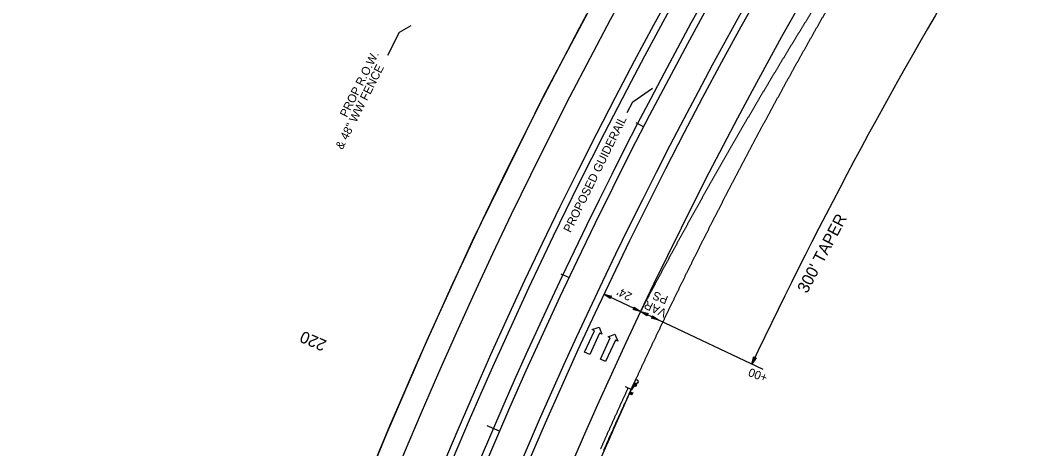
# Model space of a CAD drawing. Extents: x 2389099 to 2405615, y 552200 to 573532.
# Drawn here: x 2400105 to 2400699, y 569173 to 569428 of the extents above; entities that cross this region are included whole.
import ezdxf

# ---------------------------------------------------------------- set-up
doc = ezdxf.new("R2010")
doc.units = 0
for name, color, linetype in [('Old_Level_1', 7, 'Continuous'), ('Prop Cable Guiderail Single Face', 7, 'Continuous'), ('Prop Conc Expressway Gutter', 7, 'Continuous'), ('Prop Dimension', 7, 'Continuous'), ('Prop Dimension Text', 7, 'Continuous'), ('Prop DSN Text', 7, 'Continuous'), ('Prop EOT', 7, 'Continuous'), ('Prop Guardrail', 7, 'Continuous'), ('Prop Horizontal Alignment', 7, 'Continuous'), ('Prop Horizontal Alignment Curve and Spiral Data', 7, 'Continuous'), ('Prop Horizontal Alignment Tick Large', 7, 'Continuous'), ('Prop Horizontal Alignment Tick Small', 7, 'Continuous'), ('Prop Lane Arrow Through CELL', 7, 'Continuous'), ('Prop Lane Lines', 7, 'Continuous')]:
    doc.layers.add(name, color=color, linetype=linetype)

msp = doc.modelspace()

# ---------------------------------------------------------------- linework, layer by layer
at = {"layer": 'Old_Level_1'}
for p, q in [((2400468.37, 569210.69), (2400468.94, 569211.96)), ((2400468.83, 569211.72), (2400469.54, 569213.29)), ((2400468.94, 569211.96), (2400470.41, 569211.3)), ((2400468.94, 569211.96), (2400469.84, 569210.02)), ((2400470.66, 569211.91), (2400469.59, 569211.67)), ((2400466.06, 569205.59), (2400468.83, 569211.72)), ((2400466.06, 569205.59), (2400466.64, 569206.87)), ((2400466.06, 569205.59), (2400468.11, 569206.2)), ((2400466.64, 569206.87), (2400468.11, 569206.2)), ((2400466.64, 569206.87), (2400467.53, 569204.93)), ((2400469.39, 569210.99), (2400467.09, 569207.86)), ((2400468.11, 569206.2), (2400467.53, 569204.93)), ((2400468.37, 569210.69), (2400470.41, 569211.3)), ((2400469.84, 569210.02), (2400468.37, 569210.69)), ((2400468.83, 569211.72), (2400468.72, 569211.48)), ((2400470.41, 569211.3), (2400469.84, 569210.02)), ((2400467.53, 569204.93), (2400466.06, 569205.59))]:
    msp.add_line(p, q, dxfattribs=at)
msp.add_ellipse((2400470.45, 569212.88), major_axis=(-0.905, 0.409), ratio=0.995379, start_param=2.210226, end_param=6.283185, dxfattribs=at)
at = {"layer": 'Prop Cable Guiderail Single Face'}
msp.add_arc((2403051.7, 568034.46), 2904, 119.41161, 162.0892, dxfattribs=at)
at = {"layer": 'Prop Conc Expressway Gutter'}
msp.add_spline([(2400449.06, 569172.84), (2400449.4, 569173.61), (2400449.75, 569174.39), (2400450.09, 569175.17), (2400450.44, 569175.95), (2400450.79, 569176.73), (2400451.13, 569177.51), (2400451.48, 569178.29), (2400451.83, 569179.07), (2400452.17, 569179.83), (2400452.52, 569180.61), (2400452.86, 569181.39), (2400453.21, 569182.17), (2400453.56, 569182.95), (2400453.91, 569183.73), (2400454.26, 569184.5), (2400454.6, 569185.28), (2400454.95, 569186.05), (2400455.3, 569186.83), (2400455.65, 569187.6), (2400456, 569188.38), (2400456.35, 569189.16), (2400456.7, 569189.93), (2400457.05, 569190.71), (2400457.4, 569191.49), (2400457.75, 569192.26), (2400458.1, 569193.03), (2400458.45, 569193.81), (2400458.8, 569194.59), (2400459.15, 569195.36), (2400459.5, 569196.14), (2400459.85, 569196.91), (2400460.2, 569197.68), (2400460.56, 569198.46), (2400460.91, 569199.23), (2400461.26, 569200.01), (2400461.61, 569200.78), (2400461.97, 569201.56), (2400462.32, 569202.33), (2400462.68, 569203.11), (2400463.03, 569203.88), (2400463.38, 569204.65), (2400463.74, 569205.43), (2400464.09, 569206.2), (2400464.45, 569206.97), (2400464.8, 569207.75), (2400465.16, 569208.52), (2400465.41, 569209.08)], degree=3, dxfattribs=at)
at = {"layer": 'Prop Dimension'}
for p, q in [((2400472.73, 569254.5), (2400451.03, 569264.77)), ((2400483.58, 569249.37), (2400472.73, 569254.5)), ((2400545.52, 569220.07), (2400483.58, 569249.37))]:
    msp.add_line(p, q, dxfattribs=at)
for points in [[(2400454.77, 569262.14), (2400451.03, 569264.77), (2400455.47, 569263.55), (2400454.6, 569263.08)], [(2400468.99, 569257.13), (2400472.73, 569254.5), (2400468.3, 569255.71), (2400469.16, 569256.19)], [(2400476.47, 569251.88), (2400472.73, 569254.5), (2400477.16, 569253.29), (2400476.3, 569252.81)], [(2400479.84, 569252), (2400483.58, 569249.37), (2400479.14, 569250.58), (2400480.01, 569251.06)], [(2400541.27, 569227.07), (2400538.71, 569223.29), (2400539.84, 569227.74), (2400540.33, 569226.89)]]:
    msp.add_lwpolyline(points, close=True, dxfattribs=at)
msp.add_arc((2403051.7, 568034.46), 2780, 148.7553, 154.68244, dxfattribs=at)
at = {"layer": 'Prop DSN Text'}
for p, q in [((2400322.78, 569406.64), (2400329.86, 569420.33)), ((2400329.86, 569420.33), (2400336.73, 569424.27)), ((2400468.1, 569379.06), (2400479.81, 569387.11)), ((2400464.71, 569372.74), (2400468.1, 569379.06))]:
    msp.add_line(p, q, dxfattribs=at)
at = {"layer": 'Prop EOT'}
msp.add_line((2400463.6, 569209.92), (2400467.29, 569208.22), dxfattribs=at)
for radius, start, end in [(2923, 119.41161, 180.94658), (2919, 119.41161, 162.43732), (2881, 119.41161, 165.38993), (2877, 119.41161, 180.94658), (2961, 148.75529, 167.84172), (2947, 148.75529, 180.94658), (2853, 154.68245, 180.94658)]:
    msp.add_arc((2403051.7, 568034.46), radius, start, end, dxfattribs=at)
for points in [[(2400590.72, 569458.71), (2400590.29, 569458.04), (2400589.87, 569457.36), (2400589.44, 569456.69), (2400589.02, 569456.02), (2400588.59, 569455.35), (2400588.17, 569454.68), (2400587.74, 569454), (2400587.31, 569453.33), (2400586.89, 569452.65), (2400586.46, 569451.98), (2400586.04, 569451.31), (2400585.62, 569450.64), (2400585.19, 569449.96), (2400584.77, 569449.29), (2400584.35, 569448.62), (2400583.92, 569447.94), (2400583.5, 569447.27), (2400583.08, 569446.6), (2400582.65, 569445.92), (2400582.23, 569445.24), (2400581.81, 569444.57), (2400581.38, 569443.89), (2400580.96, 569443.22), (2400580.54, 569442.55), (2400580.12, 569441.87), (2400579.7, 569441.2), (2400579.28, 569440.52), (2400578.86, 569439.85), (2400578.44, 569439.17), (2400578.02, 569438.5), (2400577.59, 569437.82), (2400577.17, 569437.14), (2400576.75, 569436.47), (2400576.33, 569435.79), (2400575.91, 569435.11), (2400575.49, 569434.44), (2400575.07, 569433.76), (2400574.65, 569433.09), (2400574.23, 569432.41), (2400573.82, 569431.74), (2400573.4, 569431.06), (2400572.98, 569430.38), (2400572.56, 569429.71), (2400572.14, 569429.02), (2400571.72, 569428.34), (2400571.3, 569427.67), (2400570.89, 569426.99), (2400570.47, 569426.31), (2400570.05, 569425.64), (2400569.64, 569424.96), (2400569.22, 569424.28), (2400568.8, 569423.6), (2400568.39, 569422.93), (2400567.97, 569422.25), (2400567.55, 569421.57), (2400567.13, 569420.88), (2400566.72, 569420.21), (2400566.3, 569419.53), (2400565.89, 569418.85), (2400565.47, 569418.17), (2400565.06, 569417.49), (2400564.64, 569416.81), (2400564.23, 569416.13), (2400563.81, 569415.45), (2400563.4, 569414.78), (2400562.99, 569414.1), (2400562.57, 569413.42), (2400562.16, 569412.73), (2400561.74, 569412.05), (2400561.33, 569411.37), (2400560.92, 569410.69), (2400560.5, 569410.01), (2400560.09, 569409.33), (2400559.68, 569408.65)], [(2400562.85, 569397.33), (2400563.26, 569398.07), (2400563.67, 569398.81), (2400564.08, 569399.55), (2400564.49, 569400.3), (2400564.91, 569401.04), (2400565.32, 569401.78), (2400565.73, 569402.53), (2400566.15, 569403.27), (2400566.56, 569404.02), (2400566.97, 569404.76), (2400567.38, 569405.49), (2400567.8, 569406.24), (2400568.21, 569406.98), (2400568.63, 569407.72), (2400569.05, 569408.47), (2400569.46, 569409.21), (2400569.88, 569409.95), (2400570.29, 569410.69), (2400570.7, 569411.43), (2400571.12, 569412.17), (2400571.54, 569412.91), (2400571.96, 569413.66), (2400572.37, 569414.4), (2400572.79, 569415.14), (2400573.21, 569415.88), (2400573.63, 569416.62), (2400574.04, 569417.36), (2400574.46, 569418.1), (2400574.88, 569418.84), (2400575.29, 569419.58), (2400575.71, 569420.32), (2400576.13, 569421.06), (2400576.55, 569421.8), (2400576.97, 569422.54), (2400577.39, 569423.27), (2400577.81, 569424.01), (2400578.23, 569424.75), (2400578.65, 569425.49), (2400579.07, 569426.23), (2400579.49, 569426.97), (2400579.91, 569427.71), (2400580.33, 569428.45), (2400580.75, 569429.18), (2400581.17, 569429.92), (2400581.59, 569430.66), (2400582.02, 569431.4), (2400582.44, 569432.14), (2400582.86, 569432.88), (2400583.28, 569433.62), (2400583.7, 569434.35), (2400584.13, 569435.09), (2400584.55, 569435.83), (2400584.97, 569436.56), (2400585.4, 569437.3), (2400585.82, 569438.04), (2400586.25, 569438.78), (2400586.67, 569439.52), (2400587.09, 569440.24), (2400587.52, 569440.98), (2400587.94, 569441.72), (2400588.37, 569442.46), (2400588.79, 569443.19), (2400589.22, 569443.93), (2400589.65, 569444.67), (2400590.07, 569445.4), (2400590.49, 569446.13), (2400590.92, 569446.87), (2400591.35, 569447.6), (2400591.78, 569448.34), (2400592.2, 569449.08), (2400592.63, 569449.81), (2400593.06, 569450.55), (2400593.49, 569451.28), (2400593.91, 569452.01)], [(2400559.68, 569408.65), (2400559.27, 569407.97), (2400558.85, 569407.29), (2400558.44, 569406.61), (2400558.03, 569405.93), (2400557.62, 569405.24), (2400557.21, 569404.56), (2400556.79, 569403.87), (2400556.38, 569403.19), (2400555.97, 569402.51), (2400555.56, 569401.83), (2400555.15, 569401.15), (2400554.74, 569400.47), (2400554.33, 569399.78), (2400553.92, 569399.1), (2400553.51, 569398.42), (2400553.1, 569397.74), (2400552.69, 569397.06), (2400552.28, 569396.37), (2400551.87, 569395.68), (2400551.46, 569395), (2400551.05, 569394.32), (2400550.65, 569393.63), (2400550.24, 569392.95), (2400549.83, 569392.27), (2400549.42, 569391.58), (2400549.01, 569390.9), (2400548.61, 569390.22), (2400548.2, 569389.53), (2400547.79, 569388.85), (2400547.39, 569388.16), (2400546.98, 569387.47), (2400546.57, 569386.79), (2400546.16, 569386.1), (2400545.76, 569385.42), (2400545.35, 569384.73), (2400544.95, 569384.05), (2400544.54, 569383.36), (2400544.13, 569382.68), (2400543.73, 569381.99), (2400543.32, 569381.31), (2400542.92, 569380.62), (2400542.52, 569379.94), (2400542.11, 569379.25), (2400541.7, 569378.56), (2400541.3, 569377.87), (2400540.9, 569377.19), (2400540.49, 569376.5), (2400540.09, 569375.81), (2400539.68, 569375.13), (2400539.28, 569374.44), (2400538.88, 569373.75), (2400538.48, 569373.07), (2400538.07, 569372.38), (2400537.67, 569371.69), (2400537.27, 569371.01), (2400536.86, 569370.31), (2400536.46, 569369.62), (2400536.06, 569368.94), (2400535.66, 569368.25), (2400535.26, 569367.56), (2400534.86, 569366.87), (2400534.46, 569366.19), (2400534.06, 569365.5), (2400533.66, 569364.81), (2400533.25, 569364.12), (2400532.85, 569363.43), (2400532.46, 569362.74), (2400532.05, 569362.05), (2400531.65, 569361.36), (2400531.25, 569360.67), (2400530.85, 569359.98), (2400530.45, 569359.29), (2400530.06, 569358.6), (2400529.66, 569357.91)], [(2400532.99, 569341.95), (2400533.39, 569342.71), (2400533.78, 569343.46), (2400534.18, 569344.21), (2400534.58, 569344.97), (2400534.97, 569345.72), (2400535.37, 569346.47), (2400535.76, 569347.22), (2400536.16, 569347.97), (2400536.56, 569348.72), (2400536.96, 569349.48), (2400537.35, 569350.23), (2400537.75, 569350.98), (2400538.15, 569351.73), (2400538.55, 569352.48), (2400538.94, 569353.23), (2400539.34, 569353.98), (2400539.74, 569354.73), (2400540.14, 569355.48), (2400540.54, 569356.24), (2400540.94, 569356.99), (2400541.34, 569357.74), (2400541.74, 569358.48), (2400542.14, 569359.23), (2400542.54, 569359.98), (2400542.94, 569360.73), (2400543.34, 569361.48), (2400543.74, 569362.24), (2400544.15, 569362.99), (2400544.55, 569363.74), (2400544.95, 569364.48), (2400545.35, 569365.23), (2400545.75, 569365.98), (2400546.15, 569366.73), (2400546.56, 569367.48), (2400546.96, 569368.23), (2400547.36, 569368.98), (2400547.77, 569369.73), (2400548.17, 569370.47), (2400548.57, 569371.22), (2400548.98, 569371.97), (2400549.38, 569372.71), (2400549.79, 569373.46), (2400550.19, 569374.21), (2400550.6, 569374.96), (2400551, 569375.71), (2400551.4, 569376.45), (2400551.81, 569377.2), (2400552.22, 569377.94), (2400552.62, 569378.69), (2400553.03, 569379.44), (2400553.44, 569380.19), (2400553.84, 569380.94), (2400554.25, 569381.68), (2400554.66, 569382.42), (2400555.06, 569383.17), (2400555.47, 569383.92), (2400555.88, 569384.66), (2400556.29, 569385.41), (2400556.7, 569386.16), (2400557.11, 569386.9), (2400557.52, 569387.65), (2400557.92, 569388.39), (2400558.33, 569389.13), (2400558.74, 569389.88), (2400559.15, 569390.63), (2400559.56, 569391.37), (2400559.97, 569392.12), (2400560.38, 569392.86), (2400560.79, 569393.6), (2400561.2, 569394.35), (2400561.61, 569395.09), (2400562.02, 569395.84), (2400562.43, 569396.58), (2400562.85, 569397.33)], [(2400529.66, 569357.91), (2400529.26, 569357.22), (2400528.86, 569356.53), (2400528.46, 569355.84), (2400528.07, 569355.16), (2400527.67, 569354.47), (2400527.27, 569353.78), (2400526.87, 569353.08), (2400526.47, 569352.39), (2400526.08, 569351.7), (2400525.68, 569351.01), (2400525.28, 569350.31), (2400524.89, 569349.62), (2400524.49, 569348.93), (2400524.09, 569348.24), (2400523.7, 569347.55), (2400523.3, 569346.86), (2400522.91, 569346.17), (2400522.51, 569345.48), (2400522.11, 569344.78), (2400521.72, 569344.08), (2400521.32, 569343.39), (2400520.93, 569342.7), (2400520.54, 569342.01), (2400520.14, 569341.32), (2400519.75, 569340.62), (2400519.35, 569339.93), (2400518.96, 569339.24), (2400518.57, 569338.55), (2400518.18, 569337.85), (2400517.78, 569337.16), (2400517.39, 569336.46), (2400516.99, 569335.77), (2400516.6, 569335.07), (2400516.21, 569334.38), (2400515.82, 569333.69), (2400515.43, 569332.99), (2400515.03, 569332.3), (2400514.64, 569331.61), (2400514.25, 569330.91), (2400513.86, 569330.22), (2400513.47, 569329.52), (2400513.08, 569328.83), (2400512.69, 569328.14), (2400512.29, 569327.43), (2400511.9, 569326.74), (2400511.51, 569326.04), (2400511.12, 569325.35), (2400510.74, 569324.65), (2400510.35, 569323.96), (2400509.96, 569323.26), (2400509.57, 569322.57), (2400509.18, 569321.87), (2400508.79, 569321.18), (2400508.4, 569320.48), (2400508.02, 569319.78), (2400507.62, 569319.08), (2400507.24, 569318.38), (2400506.85, 569317.69), (2400506.46, 569316.99), (2400506.07, 569316.3), (2400505.69, 569315.6), (2400505.3, 569314.9), (2400504.91, 569314.21), (2400504.53, 569313.51), (2400504.14, 569312.81), (2400503.75, 569312.11), (2400503.37, 569311.42), (2400502.98, 569310.71), (2400502.59, 569310.01), (2400502.21, 569309.32), (2400501.82, 569308.62), (2400501.44, 569307.92), (2400501.05, 569307.22), (2400500.67, 569306.52)], [(2400504.38, 569285.93), (2400504.76, 569286.69), (2400505.13, 569287.45), (2400505.51, 569288.21), (2400505.89, 569288.97), (2400506.27, 569289.73), (2400506.65, 569290.5), (2400507.03, 569291.26), (2400507.41, 569292.02), (2400507.79, 569292.78), (2400508.17, 569293.53), (2400508.55, 569294.3), (2400508.93, 569295.06), (2400509.31, 569295.82), (2400509.69, 569296.58), (2400510.08, 569297.34), (2400510.46, 569298.1), (2400510.84, 569298.86), (2400511.22, 569299.61), (2400511.6, 569300.37), (2400511.99, 569301.13), (2400512.37, 569301.89), (2400512.75, 569302.65), (2400513.14, 569303.41), (2400513.52, 569304.17), (2400513.91, 569304.93), (2400514.29, 569305.68), (2400514.67, 569306.44), (2400515.06, 569307.2), (2400515.44, 569307.96), (2400515.83, 569308.72), (2400516.21, 569309.48), (2400516.6, 569310.24), (2400516.99, 569311), (2400517.37, 569311.75), (2400517.76, 569312.51), (2400518.14, 569313.26), (2400518.53, 569314.02), (2400518.92, 569314.78), (2400519.31, 569315.54), (2400519.69, 569316.3), (2400520.08, 569317.04), (2400520.47, 569317.8), (2400520.85, 569318.56), (2400521.24, 569319.32), (2400521.63, 569320.08), (2400522.02, 569320.83), (2400522.41, 569321.59), (2400522.8, 569322.35), (2400523.19, 569323.09), (2400523.58, 569323.85), (2400523.97, 569324.61), (2400524.36, 569325.36), (2400524.75, 569326.12), (2400525.14, 569326.88), (2400525.53, 569327.63), (2400525.92, 569328.39), (2400526.31, 569329.14), (2400526.7, 569329.89), (2400527.09, 569330.65), (2400527.48, 569331.4), (2400527.88, 569332.16), (2400528.27, 569332.91), (2400528.66, 569333.67), (2400529.06, 569334.42), (2400529.45, 569335.17), (2400529.84, 569335.93), (2400530.23, 569336.68), (2400530.63, 569337.43), (2400531.02, 569338.19), (2400531.42, 569338.94), (2400531.81, 569339.7), (2400532.21, 569340.45), (2400532.6, 569341.2), (2400532.99, 569341.95)], [(2400500.67, 569306.52), (2400500.29, 569305.83), (2400499.9, 569305.13), (2400499.52, 569304.43), (2400499.13, 569303.73), (2400498.75, 569303.03), (2400498.37, 569302.33), (2400497.98, 569301.63), (2400497.6, 569300.93), (2400497.21, 569300.23), (2400496.83, 569299.53), (2400496.45, 569298.83), (2400496.07, 569298.13), (2400495.69, 569297.43), (2400495.3, 569296.73), (2400494.92, 569296.03), (2400494.54, 569295.33), (2400494.16, 569294.63), (2400493.78, 569293.93), (2400493.39, 569293.22), (2400493.01, 569292.52), (2400492.63, 569291.82), (2400492.25, 569291.12), (2400491.87, 569290.42), (2400491.49, 569289.72), (2400491.11, 569289.02), (2400490.73, 569288.32), (2400490.35, 569287.62), (2400489.98, 569286.92), (2400489.6, 569286.22), (2400489.22, 569285.51), (2400488.83, 569284.8), (2400488.46, 569284.1), (2400488.08, 569283.4), (2400487.7, 569282.7), (2400487.32, 569282), (2400486.94, 569281.29), (2400486.57, 569280.59), (2400486.19, 569279.89), (2400485.81, 569279.19), (2400485.44, 569278.48), (2400485.06, 569277.78), (2400484.68, 569277.08), (2400484.31, 569276.38), (2400483.93, 569275.66), (2400483.55, 569274.96), (2400483.18, 569274.26), (2400482.8, 569273.55), (2400482.43, 569272.85), (2400482.05, 569272.15), (2400481.68, 569271.44), (2400481.3, 569270.74), (2400480.93, 569270.04), (2400480.55, 569269.33), (2400480.18, 569268.63), (2400479.8, 569267.92), (2400479.43, 569267.21), (2400479.05, 569266.51), (2400478.68, 569265.8), (2400478.31, 569265.1), (2400477.93, 569264.39), (2400477.56, 569263.69), (2400477.19, 569262.98), (2400476.82, 569262.28), (2400476.44, 569261.57), (2400476.07, 569260.87), (2400475.7, 569260.16), (2400475.33, 569259.45), (2400474.95, 569258.74), (2400474.58, 569258.03), (2400474.21, 569257.33), (2400473.84, 569256.62), (2400473.47, 569255.92), (2400472.73, 569254.5)], [(2400477, 569229.28), (2400477.36, 569230.05), (2400477.73, 569230.82), (2400478.09, 569231.59), (2400478.45, 569232.36), (2400478.81, 569233.13), (2400479.17, 569233.89), (2400479.54, 569234.66), (2400479.9, 569235.43), (2400480.26, 569236.2), (2400480.63, 569236.97), (2400480.99, 569237.74), (2400481.36, 569238.51), (2400481.72, 569239.27), (2400482.08, 569240.04), (2400482.45, 569240.81), (2400482.81, 569241.58), (2400483.18, 569242.35), (2400483.55, 569243.12), (2400483.91, 569243.89), (2400484.28, 569244.65), (2400484.64, 569245.41), (2400485.01, 569246.18), (2400485.38, 569246.95), (2400485.74, 569247.72), (2400486.11, 569248.49), (2400486.48, 569249.25), (2400486.85, 569250.02), (2400487.21, 569250.79), (2400487.58, 569251.55), (2400487.95, 569252.32), (2400488.32, 569253.08), (2400488.69, 569253.85), (2400489.05, 569254.62), (2400489.42, 569255.39), (2400489.79, 569256.15), (2400490.16, 569256.92), (2400490.53, 569257.68), (2400490.9, 569258.44), (2400491.27, 569259.21), (2400491.64, 569259.98), (2400492.01, 569260.74), (2400492.39, 569261.51), (2400492.76, 569262.28), (2400493.13, 569263.04), (2400493.5, 569263.8), (2400493.87, 569264.56), (2400494.24, 569265.33), (2400494.62, 569266.1), (2400494.99, 569266.86), (2400495.36, 569267.63), (2400495.73, 569268.39), (2400496.11, 569269.16), (2400496.48, 569269.91), (2400496.85, 569270.68), (2400497.23, 569271.44), (2400497.6, 569272.21), (2400497.98, 569272.97), (2400498.35, 569273.74), (2400498.73, 569274.5), (2400499.1, 569275.25), (2400499.47, 569276.02), (2400499.85, 569276.78), (2400500.23, 569277.55), (2400500.6, 569278.31), (2400500.98, 569279.07), (2400501.36, 569279.84), (2400501.73, 569280.6), (2400502.11, 569281.36), (2400502.48, 569282.12), (2400502.86, 569282.88), (2400503.24, 569283.64), (2400503.62, 569284.41), (2400504, 569285.17), (2400504.38, 569285.93)], [(2400450.89, 569172.03), (2400451.23, 569172.8), (2400451.58, 569173.58), (2400451.92, 569174.36), (2400452.27, 569175.14), (2400452.61, 569175.92), (2400452.96, 569176.7), (2400453.31, 569177.47), (2400453.65, 569178.25), (2400454, 569179.02), (2400454.34, 569179.8), (2400454.69, 569180.58), (2400455.04, 569181.35), (2400455.39, 569182.13), (2400455.73, 569182.91), (2400456.08, 569183.68), (2400456.43, 569184.46), (2400456.77, 569185.23), (2400457.12, 569186.01), (2400457.47, 569186.78), (2400457.82, 569187.56), (2400458.17, 569188.34), (2400458.52, 569189.11), (2400458.87, 569189.89), (2400459.22, 569190.67), (2400459.57, 569191.43), (2400459.92, 569192.21), (2400460.27, 569192.98), (2400460.62, 569193.76), (2400460.97, 569194.54), (2400461.32, 569195.31), (2400461.68, 569196.09), (2400462.02, 569196.85), (2400462.38, 569197.63), (2400462.73, 569198.4), (2400463.08, 569199.18), (2400463.43, 569199.95), (2400463.79, 569200.73), (2400464.14, 569201.5), (2400464.5, 569202.28), (2400464.85, 569203.04), (2400465.2, 569203.82), (2400465.55, 569204.59), (2400465.91, 569205.37), (2400466.26, 569206.14), (2400466.62, 569206.92), (2400466.97, 569207.69), (2400467.33, 569208.46), (2400467.68, 569209.23), (2400468.04, 569210), (2400468.39, 569210.77), (2400468.75, 569211.55), (2400469.11, 569212.32), (2400469.46, 569213.09), (2400469.82, 569213.87), (2400470.18, 569214.64), (2400470.53, 569215.4), (2400470.89, 569216.18), (2400471.25, 569216.95), (2400471.61, 569217.72), (2400471.97, 569218.49), (2400472.32, 569219.27), (2400472.68, 569220.04), (2400473.04, 569220.81), (2400473.4, 569221.57), (2400473.76, 569222.35), (2400474.12, 569223.12), (2400474.48, 569223.89), (2400474.84, 569224.66), (2400475.2, 569225.43), (2400475.56, 569226.2), (2400475.92, 569226.97), (2400476.28, 569227.74), (2400476.64, 569228.51), (2400477, 569229.28)]]:
    msp.add_spline(points, degree=3, dxfattribs=at)
at = {"layer": 'Prop Guardrail'}
for p, q in [((2400446.31, 569441.34), (2400415.2, 569382.52)), ((2400415.2, 569382.52), (2400372.81, 569296.18)), ((2400372.81, 569296.18), (2400345.96, 569237.27)), ((2400345.96, 569237.27), (2400322.06, 569181.83)), ((2400322.06, 569181.83), (2400305.12, 569140.9))]:
    msp.add_line(p, q, dxfattribs=at)
msp.add_arc((2403040.3, 568035.81), 2827.56, 155.56213, 168.25722, dxfattribs=at)
at = {"layer": 'Prop Horizontal Alignment'}
msp.add_arc((2403051.7, 568034.46), 2900, 119.41161, 180.94658, dxfattribs=at)
at = {"layer": 'Prop Horizontal Alignment Tick Large'}
msp.add_line((2400389.05, 569183.49), (2400381.7, 569186.66), dxfattribs=at)
at = {"layer": 'Prop Horizontal Alignment Tick Small'}
for p, q in [((2400474.56, 569364.24), (2400470.11, 569366.53)), ((2400430.24, 569274.6), (2400425.72, 569276.74))]:
    msp.add_line(p, q, dxfattribs=at)
at = {"layer": 'Prop Lane Arrow Through CELL'}
for p, q in [((2400439.56, 569230.36), (2400445.38, 569243.09)), ((2400448.38, 569241.72), (2400442.56, 569228.99)), ((2400444.02, 569243.71), (2400448.15, 569245.29)), ((2400445.38, 569243.09), (2400444.02, 569243.71)), ((2400448.15, 569245.29), (2400449.75, 569241.09)), ((2400449.75, 569241.09), (2400448.38, 569241.72)), ((2400448.97, 569226.19), (2400454.8, 569238.92)), ((2400457.8, 569237.54), (2400451.97, 569224.81)), ((2400453.44, 569239.54), (2400457.57, 569241.11)), ((2400454.8, 569238.92), (2400453.44, 569239.54)), ((2400457.57, 569241.11), (2400459.17, 569236.92)), ((2400459.17, 569236.92), (2400457.8, 569237.54)), ((2400442.56, 569228.99), (2400439.56, 569230.36)), ((2400451.97, 569224.81), (2400448.97, 569226.19))]:
    msp.add_line(p, q, dxfattribs=at)
at = {"layer": 'Prop Lane Lines'}
msp.add_arc((2403051.7, 568034.46), 2853, 131.16509, 154.68244, dxfattribs=at)

# ---------------------------------------------------------------- texts
at = {"layer": 'Prop Dimension Text'}
for s, height, rotation, p in [("300' TAPER", 7, 62.18983, (2400571.45, 569264.82)), ("24'", 5, 152.306, (2400468.17, 569264.94)), ('PS', 5, 157.92804, (2400489.53, 569263.3)), ('VAR', 5, 154.58214, (2400488.73, 569255.27)), ('+00', 5, 159.38071, (2400548.52, 569217.06))]:
    msp.add_text(s, height=height, rotation=rotation, dxfattribs=at).set_placement(p)
at = {"layer": 'Prop DSN Text'}
for s, rotation, p in [('PROP R.O.W.', 63.33061, (2400298.55, 569369.39)), ('& 48" WW FENCE', 63.33061, (2400295.96, 569350.3)), ('PROPOSED GUIDERAIL', 63.85334, (2400431.2, 569300.95))]:
    msp.add_text(s, height=5, rotation=rotation, dxfattribs=at).set_placement(p)
at = {"layer": 'Prop Horizontal Alignment Curve and Spiral Data'}
msp.add_text('220', height=7, rotation=156.65815, dxfattribs=at).set_placement((2400287.04, 569237))

doc.saveas('drawing.dxf')
